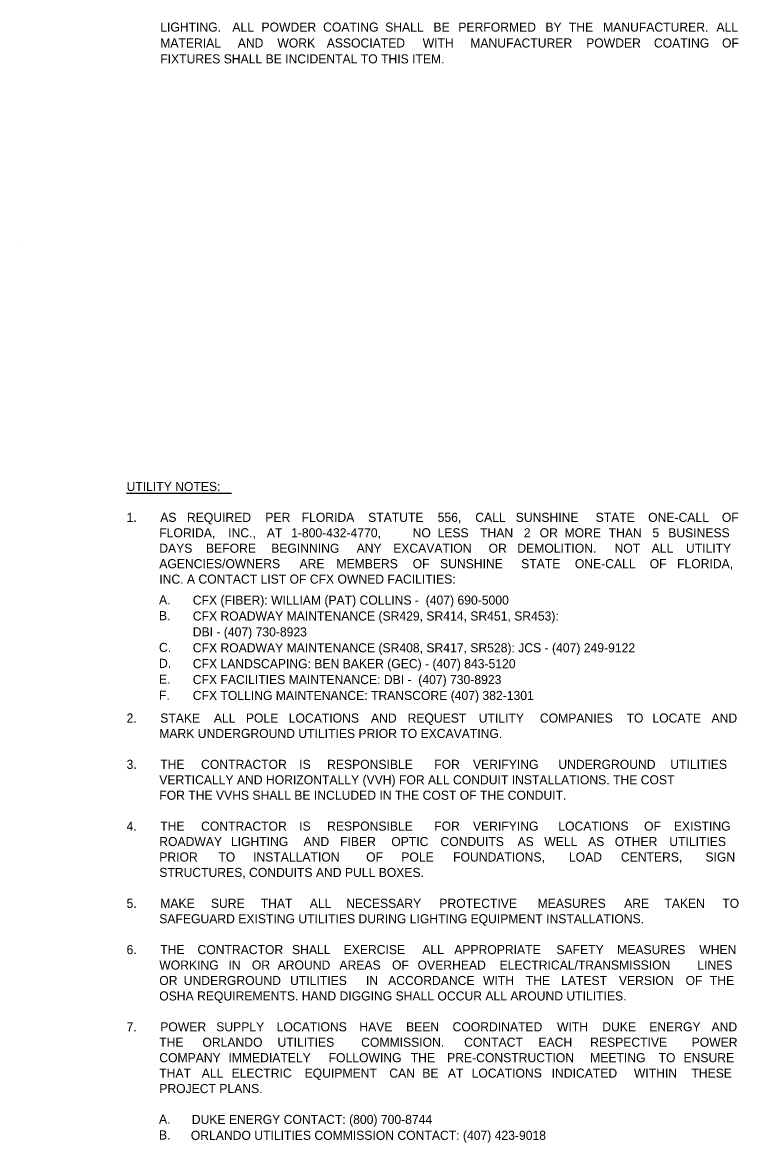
# Model space of a CAD drawing. Extents: x -55 to 2471539, y -90 to 3608906.
# Drawn here: x -54 to 497, y 1664 to 2527 of the extents above; entities that cross this region are included whole.
import ezdxf

# ---------------------------------------------------------------- set-up
doc = ezdxf.new("R2010")
doc.units = 0
doc.layers.add('TextMinor', color=7, linetype='Continuous')
doc.layers.add('XSCell', color=7, linetype='Continuous')

msp = doc.modelspace()

# ---------------------------------------------------------------- linework, layer by layer
at = {"layer": 'TextMinor'}
msp.add_line((-54.3, 2356.32), (-54.3, 2356.32), dxfattribs=at)
at = {"layer": 'XSCell'}
msp.add_line((25.94, 2164.17), (106.73, 2164.17), dxfattribs=at)

# ---------------------------------------------------------------- texts
for s, p in [('LIGHTING. ', (51.88, 2519.99)), ('ALL ', (107.43, 2519.99)), ('POWDER ', (129.85, 2519.99)), ('COATING ', (177.35, 2519.99)), ('SHALL ', (225.14, 2519.99)), ('BE ', (262.3, 2519.99)), ('PERFORMED ', (281.51, 2519.99)), ('BY ', (348.58, 2519.99)), ('THE ', (366.62, 2519.99)), ('MANUFACTURER. ', (393, 2519.99)), ('ALL ', (480.31, 2519.99)), ('MATERIAL ', (51.88, 2507.74)), ('AND ', (111.57, 2507.74)), ('WORK ', (142.09, 2507.74)), ('ASSOCIATED ', (180.12, 2507.74)), ('WITH ', (254.04, 2507.74)), ('MANUFACTURER ', (290.68, 2507.74)), ('POWDER ', (379.98, 2507.74)), ('COATING ', (432.15, 2507.74)), ('OF ', (484.61, 2507.74)), ('FIXTURES SHALL BE INCIDENTAL TO THIS ITEM.', (51.88, 2495.49)), ('UTILITY NOTES:', (25.93, 2165.88)), ('1.', (25.93, 2142.08)), ('AS ', (51.88, 2142.08)), ('REQUIRED ', (72.45, 2142.08)), ('PER ', (132.84, 2142.08)), ('FLORIDA ', (160.8, 2142.08)), ('STATUTE ', (212.02, 2142.08)), ('556, ', (265.56, 2142.08)), ('CALL ', (294.55, 2142.08)), ('SUNSHINE ', (325.71, 2142.08)), ('STATE ', (387.26, 2142.08)), ('ONE-CALL ', (427.72, 2142.08)), ('OF ', (484.48, 2142.08)), ('FLORIDA, ', (51.12, 2130.18)), ('INC., ', (104.23, 2130.18)), ('AT ', (133.98, 2130.18)), ('1-800-432-4770, ', (152.68, 2130.18)), ('NO ', (246.28, 2130.18)), ('LESS ', (265.49, 2130.18)), ('THAN ', (298.24, 2130.18)), ('2 ', (331.94, 2130.18)), ('OR ', (344.13, 2130.18)), ('MORE ', (363.28, 2130.18)), ('THAN ', (397.29, 2130.18)), ('5 ', (430.99, 2130.18)), ('BUSINESS ', (443.18, 2130.18)), ('DAYS ', (51.12, 2118.28)), ('BEFORE ', (87.13, 2118.28)), ('BEGINNING ', (137.34, 2118.28)), ('ANY ', (203.14, 2118.28)), ('EXCAVATION ', (231.32, 2118.28)), ('OR ', (304.81, 2118.28)), ('DEMOLITION. ', (326.96, 2118.28)), ('NOT ', (401.82, 2118.28)), ('ALL ', (430.4, 2118.28)), ('UTILITY ', (456.81, 2118.28)), ('AGENCIES/OWNERS ', (51.12, 2106.38)), ('ARE ', (159.16, 2106.38)), ('MEMBERS ', (187.58, 2106.38)), ('OF ', (246.33, 2106.38)), ('SUNSHINE ', (267.4, 2106.38)), ('STATE ', (329.87, 2106.38)), ('ONE-CALL ', (371.24, 2106.38)), ('OF ', (428.91, 2106.38)), ('FLORIDA, ', (449.99, 2106.38)), ('INC. A CONTACT LIST OF CFX OWNED FACILITIES:', (51.12, 2094.48)), ('A.', (50.92, 2078.56)), ('CFX (FIBER): WILLIAM (PAT) COLLINS -  (407) 690-5000', (76.93, 2078.29)), ('B.', (50.92, 2066.31)), ('CFX ROADWAY MAINTENANCE (SR429, SR414, SR451, SR453): ', (76.93, 2066.04)), ('DBI - (407) 730-8923', (76.93, 2053.79)), ('C.', (50.92, 2041.81)), ('CFX ROADWAY MAINTENANCE (SR408, SR417, SR528): JCS - (407) 249-9122', (76.93, 2041.54)), ('D.', (50.92, 2029.56)), ('CFX LANDSCAPING: BEN BAKER (GEC) - (407) 843-5120', (76.93, 2029.29)), ('E.', (50.92, 2017.31)), ('CFX FACILITIES MAINTENANCE: DBI -  (407) 730-8923', (76.93, 2017.04)), ('F.', (50.92, 2005.06)), ('CFX TOLLING MAINTENANCE: TRANSCORE (407) 382-1301', (76.93, 2004.79)), ('2.', (25.93, 1987.38)), ('STAKE ', (51.88, 1987.38)), ('ALL ', (93.17, 1987.38)), ('POLE ', (117.82, 1987.38)), ('LOCATIONS ', (150.88, 1987.38)), ('AND ', (214.2, 1987.38)), ('REQUEST ', (242.38, 1987.38)), ('UTILITY ', (297.2, 1987.38)), ('COMPANIES ', (344.33, 1987.38)), ('TO ', (411.09, 1987.38)), ('LOCATE ', (430.98, 1987.38)), ('AND ', (476.52, 1987.38)), ('MARK UNDERGROUND UTILITIES PRIOR TO EXCAVATING.', (51.12, 1975.48)), ('3.', (25.93, 1951.68)), ('THE ', (51.88, 1951.68)), ('CONTRACTOR ', (83.33, 1951.68)), ('IS ', (158.93, 1951.68)), ('RESPONSIBLE ', (180.41, 1951.68)), ('FOR ', (262.92, 1951.68)), ('VERIFYING ', (292.77, 1951.68)), ('UNDERGROUND ', (358.54, 1951.68)), ('UTILITIES ', (444.75, 1951.68)), ('VERTICALLY AND HORIZONTALLY (VVH) FOR ALL CONDUIT INSTALLATIONS. THE COST ', (51.12, 1939.78)), ('FOR THE VVHS SHALL BE INCLUDED IN THE COST OF THE CONDUIT.', (51.12, 1927.88)), ('4.', (25.93, 1904.08)), ('THE ', (51.88, 1904.08)), ('CONTRACTOR ', (83.33, 1904.08)), ('IS ', (158.92, 1904.08)), ('RESPONSIBLE ', (180.4, 1904.08)), ('FOR ', (262.91, 1904.08)), ('VERIFYING ', (292.75, 1904.08)), ('LOCATIONS ', (358.52, 1904.08)), ('OF ', (424.58, 1904.08)), ('EXISTING ', (447.54, 1904.08)), ('ROADWAY ', (51.12, 1892.18)), ('LIGHTING ', (106.3, 1892.18)), ('AND ', (162.24, 1892.18)), ('FIBER ', (190.41, 1892.18)), ('OPTIC ', (229.87, 1892.18)), ('CONDUITS ', (267.7, 1892.18)), ('AS ', (327.08, 1892.18)), ('WELL ', (347.7, 1892.18)), ('AS ', (381.42, 1892.18)), ('OTHER ', (402.04, 1892.18)), ('UTILITIES ', (444, 1892.18)), ('PRIOR ', (51.12, 1880.28)), ('TO ', (96.64, 1880.28)), ('INSTALLATION ', (123.39, 1880.28)), ('OF ', (210.46, 1880.28)), ('POLE ', (237.55, 1880.28)), ('FOUNDATIONS, ', (277.47, 1880.28)), ('LOAD ', (366.67, 1880.28)), ('CENTERS, ', (406.69, 1880.28)), ('SIGN ', (471.85, 1880.28)), ('STRUCTURES, CONDUITS AND PULL BOXES.', (51.12, 1868.38)), ('5.', (25.93, 1844.58)), ('MAKE ', (51.88, 1844.58)), ('SURE ', (90.88, 1844.58)), ('THAT ', (129.25, 1844.58)), ('ALL ', (167.06, 1844.58)), ('NECESSARY ', (195.14, 1844.58)), ('PROTECTIVE ', (266.87, 1844.58)), ('MEASURES ', (342.5, 1844.58)), ('ARE ', (409.22, 1844.58)), ('TAKEN ', (440.22, 1844.58)), ('TO ', (484.81, 1844.58)), ('SAFEGUARD EXISTING UTILITIES DURING LIGHTING EQUIPMENT INSTALLATIONS.', (51.12, 1832.68)), ('6.', (25.93, 1808.88)), ('THE ', (51.88, 1808.88)), ('CONTRACTOR ', (80.56, 1808.88)), ('SHALL ', (153.39, 1808.88)), ('EXERCISE ', (193.15, 1808.88)), ('ALL ', (253.73, 1808.88)), ('APPROPRIATE ', (278.35, 1808.88)), ('SAFETY ', (357.05, 1808.88)), ('MEASURES ', (403.81, 1808.88)), ('WHEN ', (467.07, 1808.88)), ('WORKING ', (51.12, 1796.98)), ('IN ', (104.36, 1796.98)), ('OR ', (122.44, 1796.98)), ('AROUND ', (142.3, 1796.98)), ('AREAS ', (189.9, 1796.98)), ('OF ', (230.43, 1796.98)), ('OVERHEAD ', (250.13, 1796.98)), ('ELECTRICAL/TRANSMISSION ', (313.25, 1796.98)), ('LINES ', (465.57, 1796.98)), ('OR ', (51.12, 1785.08)), ('UNDERGROUND ', (69.97, 1785.08)), ('UTILITIES ', (151.91, 1785.08)), ('IN ', (210.32, 1785.08)), ('ACCORDANCE ', (227.4, 1785.08)), ('WITH ', (300.52, 1785.08)), ('THE ', (333.46, 1785.08)), ('LATEST ', (360.64, 1785.08)), ('VERSION ', (405.17, 1785.08)), ('OF ', (456.54, 1785.08)), ('THE ', (475.23, 1785.08)), ('OSHA REQUIREMENTS. HAND DIGGING SHALL OCCUR ALL AROUND UTILITIES.', (51.12, 1773.18)), ('7.', (25.93, 1749.38)), ('POWER ', (51.88, 1749.38)), ('SUPPLY ', (95, 1749.38)), ('LOCATIONS ', (141.53, 1749.38)), ('HAVE ', (205.24, 1749.38)), ('BEEN ', (241.22, 1749.38)), ('COORDINATED ', (277.03, 1749.38)), ('WITH ', (357.5, 1749.38)), ('DUKE ', (392.36, 1749.38)), ('ENERGY ', (428.57, 1749.38)), ('AND ', (476.52, 1749.38)), ('THE ', (51.12, 1737.48)), ('ORLANDO ', (84.35, 1737.48)), ('UTILITIES ', (142.2, 1737.48)), ('COMMISSION. ', (206.65, 1737.48)), ('CONTACT ', (285.96, 1737.48)), ('EACH ', (343.21, 1737.48)), ('RESPECTIVE ', (383.03, 1737.48)), ('POWER ', (461.2, 1737.48)), ('COMPANY ', (51.12, 1725.58)), ('IMMEDIATELY ', (104.38, 1725.58)), ('FOLLOWING ', (181.58, 1725.58)), ('THE ', (244.82, 1725.58)), ('PRE-CONSTRUCTION ', (272.86, 1725.58)), ('MEETING ', (383.03, 1725.58)), ('TO ', (435.74, 1725.58)), ('ENSURE ', (454.94, 1725.58)), ('THAT ', (51.12, 1713.68)), ('ALL ', (83.84, 1713.68)), ('ELECTRIC ', (106.84, 1713.68)), ('EQUIPMENT ', (163.06, 1713.68)), ('CAN ', (228.33, 1713.68)), ('BE ', (253.73, 1713.68)), ('AT ', (273.43, 1713.68)), ('LOCATIONS ', (291.71, 1713.68)), ('INDICATED ', (353.38, 1713.68)), ('WITHIN ', (416.73, 1713.68)), ('THESE ', (461.02, 1713.68)), ('PROJECT PLANS.', (51.12, 1701.78)), ('A.', (50.92, 1678.25)), ('DUKE ENERGY CONTACT: (800) 700-8744', (76.18, 1677.98)), ('B.', (50.92, 1666)), ('ORLANDO UTILITIES COMMISSION CONTACT: (407) 423-9018', (75.42, 1665.73))]:
    msp.add_text(s, height=7, dxfattribs=at).set_placement(p)

doc.saveas('drawing.dxf')
